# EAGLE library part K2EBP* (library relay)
UNIQUELY DESIGNED RELAY NAiS Source: http://www.mew-europe.com/.. en_ds_61013_0000.pdf
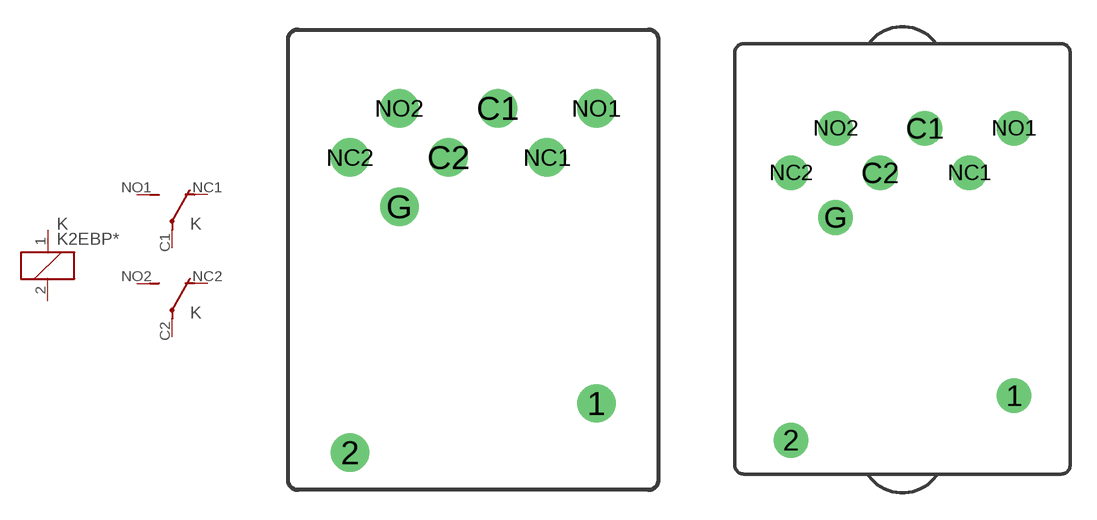
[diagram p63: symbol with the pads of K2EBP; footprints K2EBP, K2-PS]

Designator prefix K; gates _=K 1=U 2=U

## K2EBP-3V-1 (OC_FARNELL: unknown; OC_NEWARK: unknown), K2EBP-6V-1 (OC_FARNELL: unknown; OC_NEWARK: unknown), K2EBP-12V-1 (OC_FARNELL: unknown; OC_NEWARK: unknown), K2EBP-24V-1 (OC_FARNELL: unknown; OC_NEWARK: unknown), K2EBP-28V-1 (OC_FARNELL: unknown; OC_NEWARK: unknown), K2EBP-48V-1 (OC_FARNELL: unknown; OC_NEWARK: unknown), K2EBP-110V-1 (OC_FARNELL: unknown; OC_NEWARK: unknown)  [K2EBP]
1  _:1  pas
2  _:2  pas
C1  1:P  pas
C2  2:P  pas
NC1  1:O  pas
NC2  2:O  pas
NO1  1:S  pas
NO2  2:S  pas

## K2EBPS (OC_FARNELL: unknown; OC_NEWARK: unknown)  [K2-PS]
Pads as for K2EBP

## Footprint K2EBP (pad centres in mm)
UNIQUELY DESIGNED RELAY NAiS Source: http://www.mew-europe.com/.. en_ds_61013_0000.pdf
drill 1.3 round: 1 6.25,-6.25; 2 -6.25,-8.75; C1 1.25,8.75; C2 -1.25,6.25; G -3.75,3.75; NC1 3.75,6.25; NC2 -6.25,6.25; NO1 6.25,8.75; NO2 -3.75,8.75

## Footprint K2-PS (pad centres in mm)
RELAY Socked NAiS Source: http://www.mew-europe.com/.. en_ds_61013_0000.pdf
drill 1.3 round: 1 6.25,-6.25; 2 -6.25,-8.75; C1 1.25,8.75; C2 -1.25,6.25; G -3.75,3.75; NC1 3.75,6.25; NC2 -6.25,6.25; NO1 6.25,8.75; NO2 -3.75,8.75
